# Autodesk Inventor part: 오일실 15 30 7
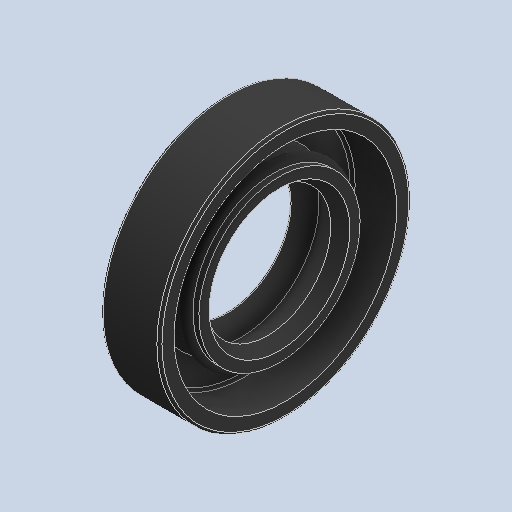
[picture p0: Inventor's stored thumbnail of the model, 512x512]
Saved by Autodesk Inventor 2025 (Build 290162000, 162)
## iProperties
Created: 2024-07
Part Number: 오일실 15 30 7
Material: 고무
Description: 오일-실
Document SubType Name: Modeling
Designer: samsung
Density: 0.93 g/cm^3
Appearance: 기본값
Author: jhkim
Sending System: Autodesk Inventor 2025
Preprocessor: ST-DEVELOPER v20
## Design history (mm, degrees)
feature "Solid1"
node "솔리드1"
